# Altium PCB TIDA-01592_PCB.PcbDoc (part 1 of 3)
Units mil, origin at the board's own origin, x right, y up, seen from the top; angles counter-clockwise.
Board outline 2047.24 x 4291.34 mil, 4 copper layers (Top Layer, GND, PWR, Bottom Layer), stack 61.6 mil thick; 218 components, 89 nets, 503 pads, 366 vias.
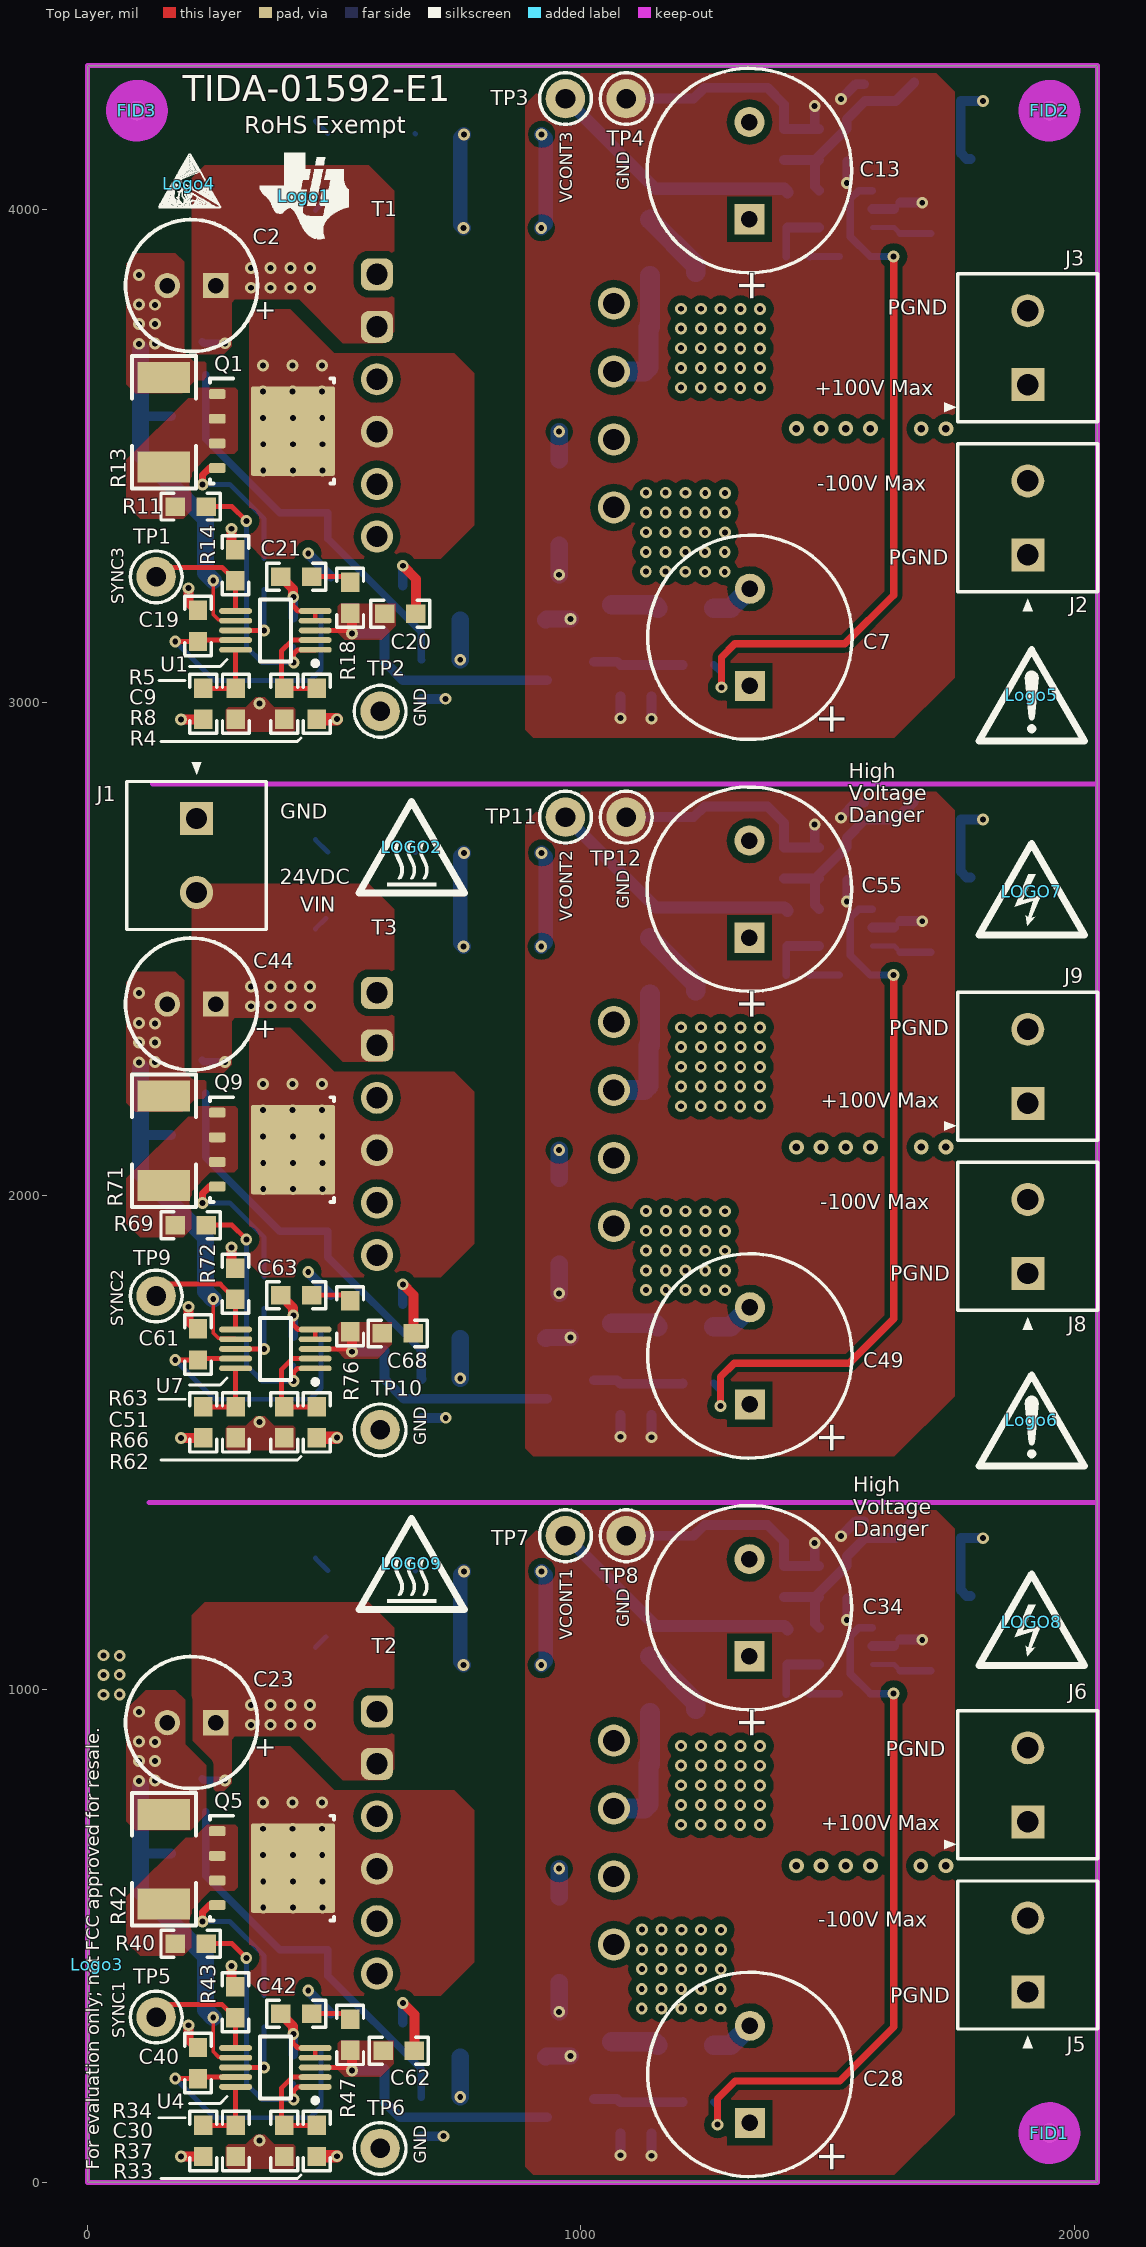
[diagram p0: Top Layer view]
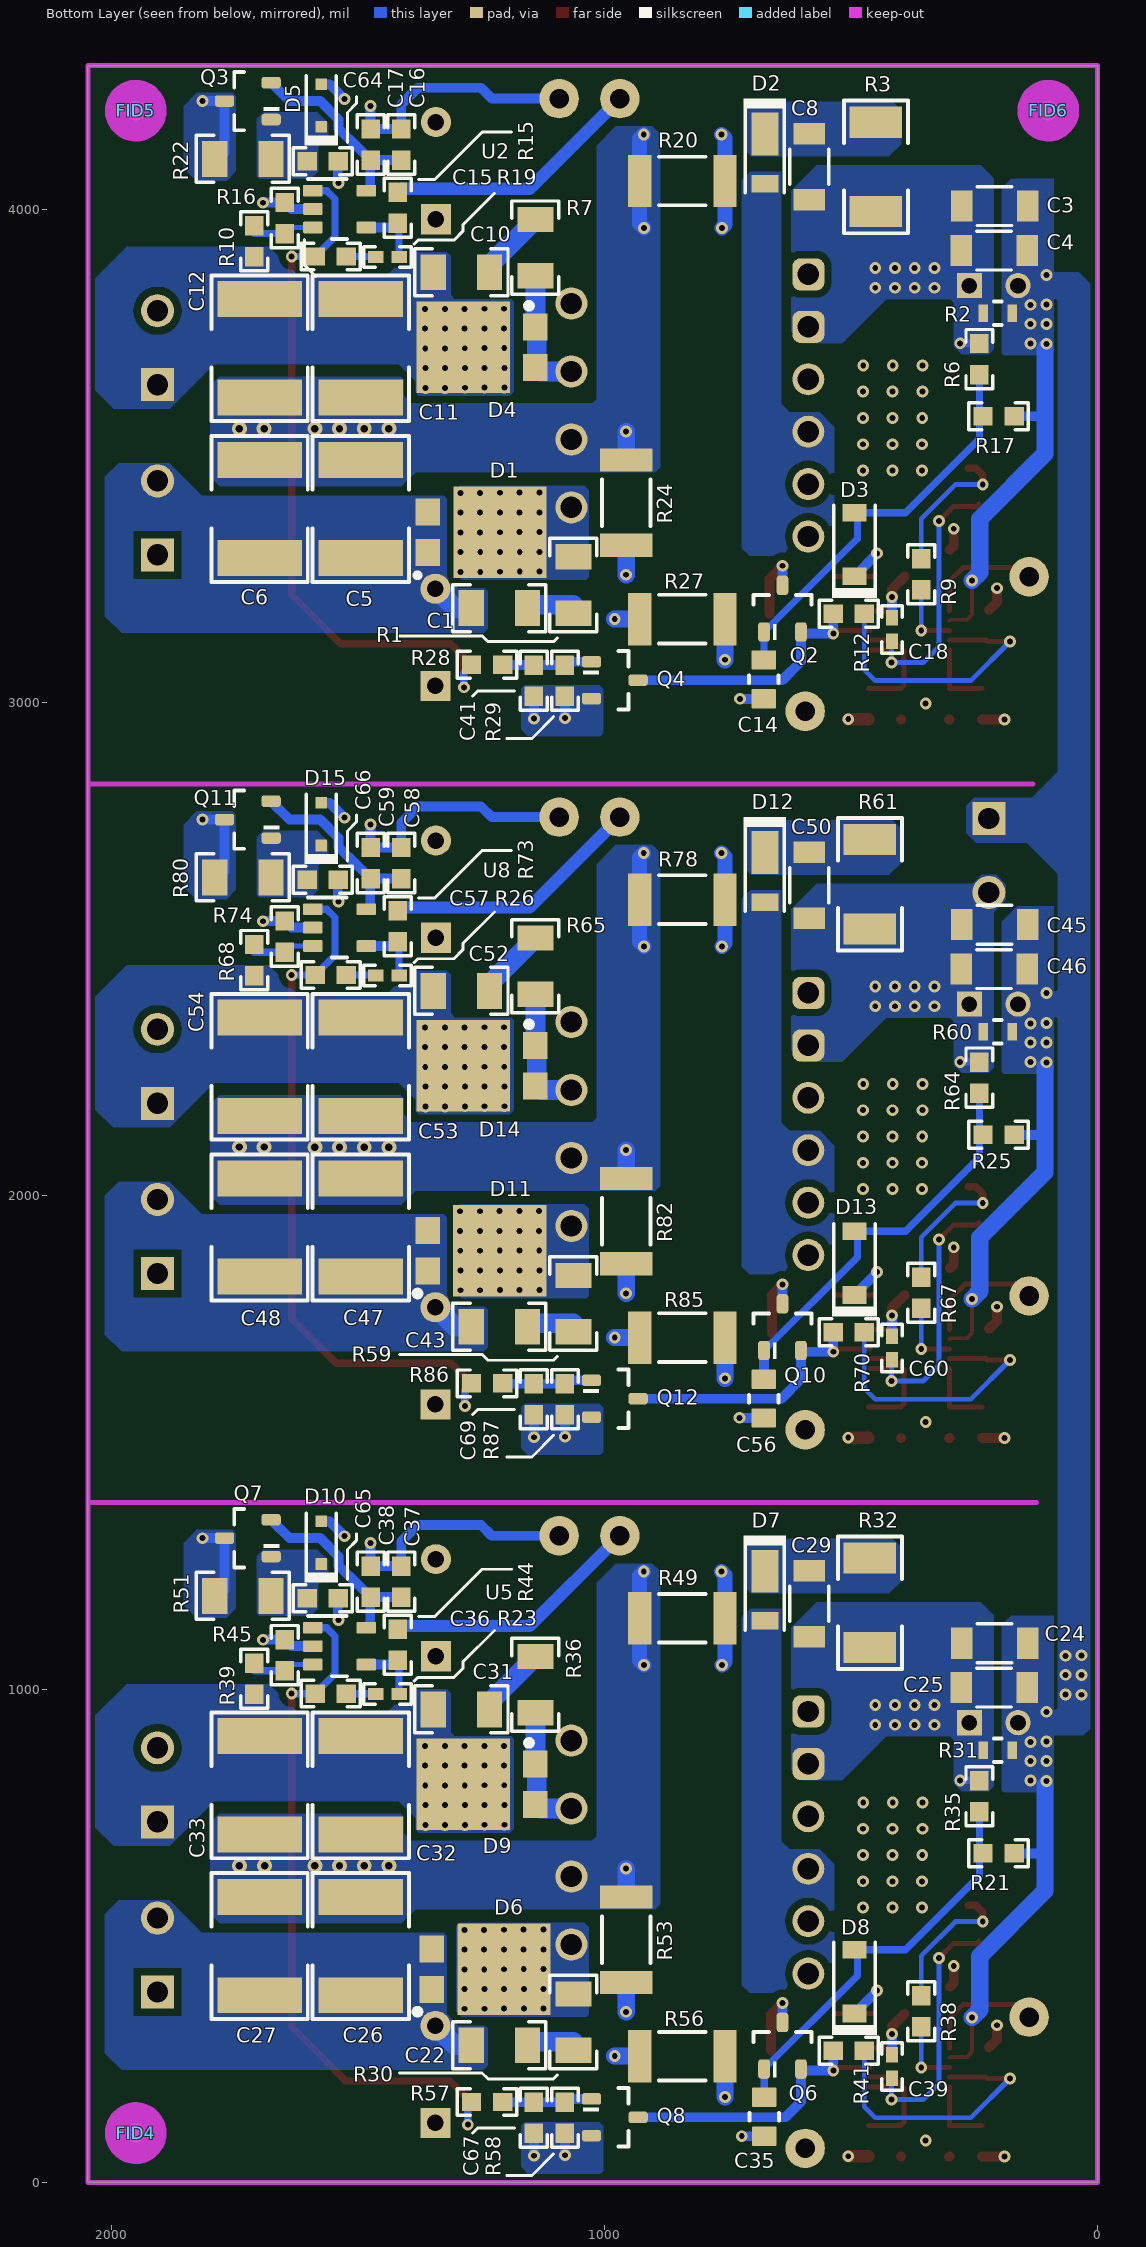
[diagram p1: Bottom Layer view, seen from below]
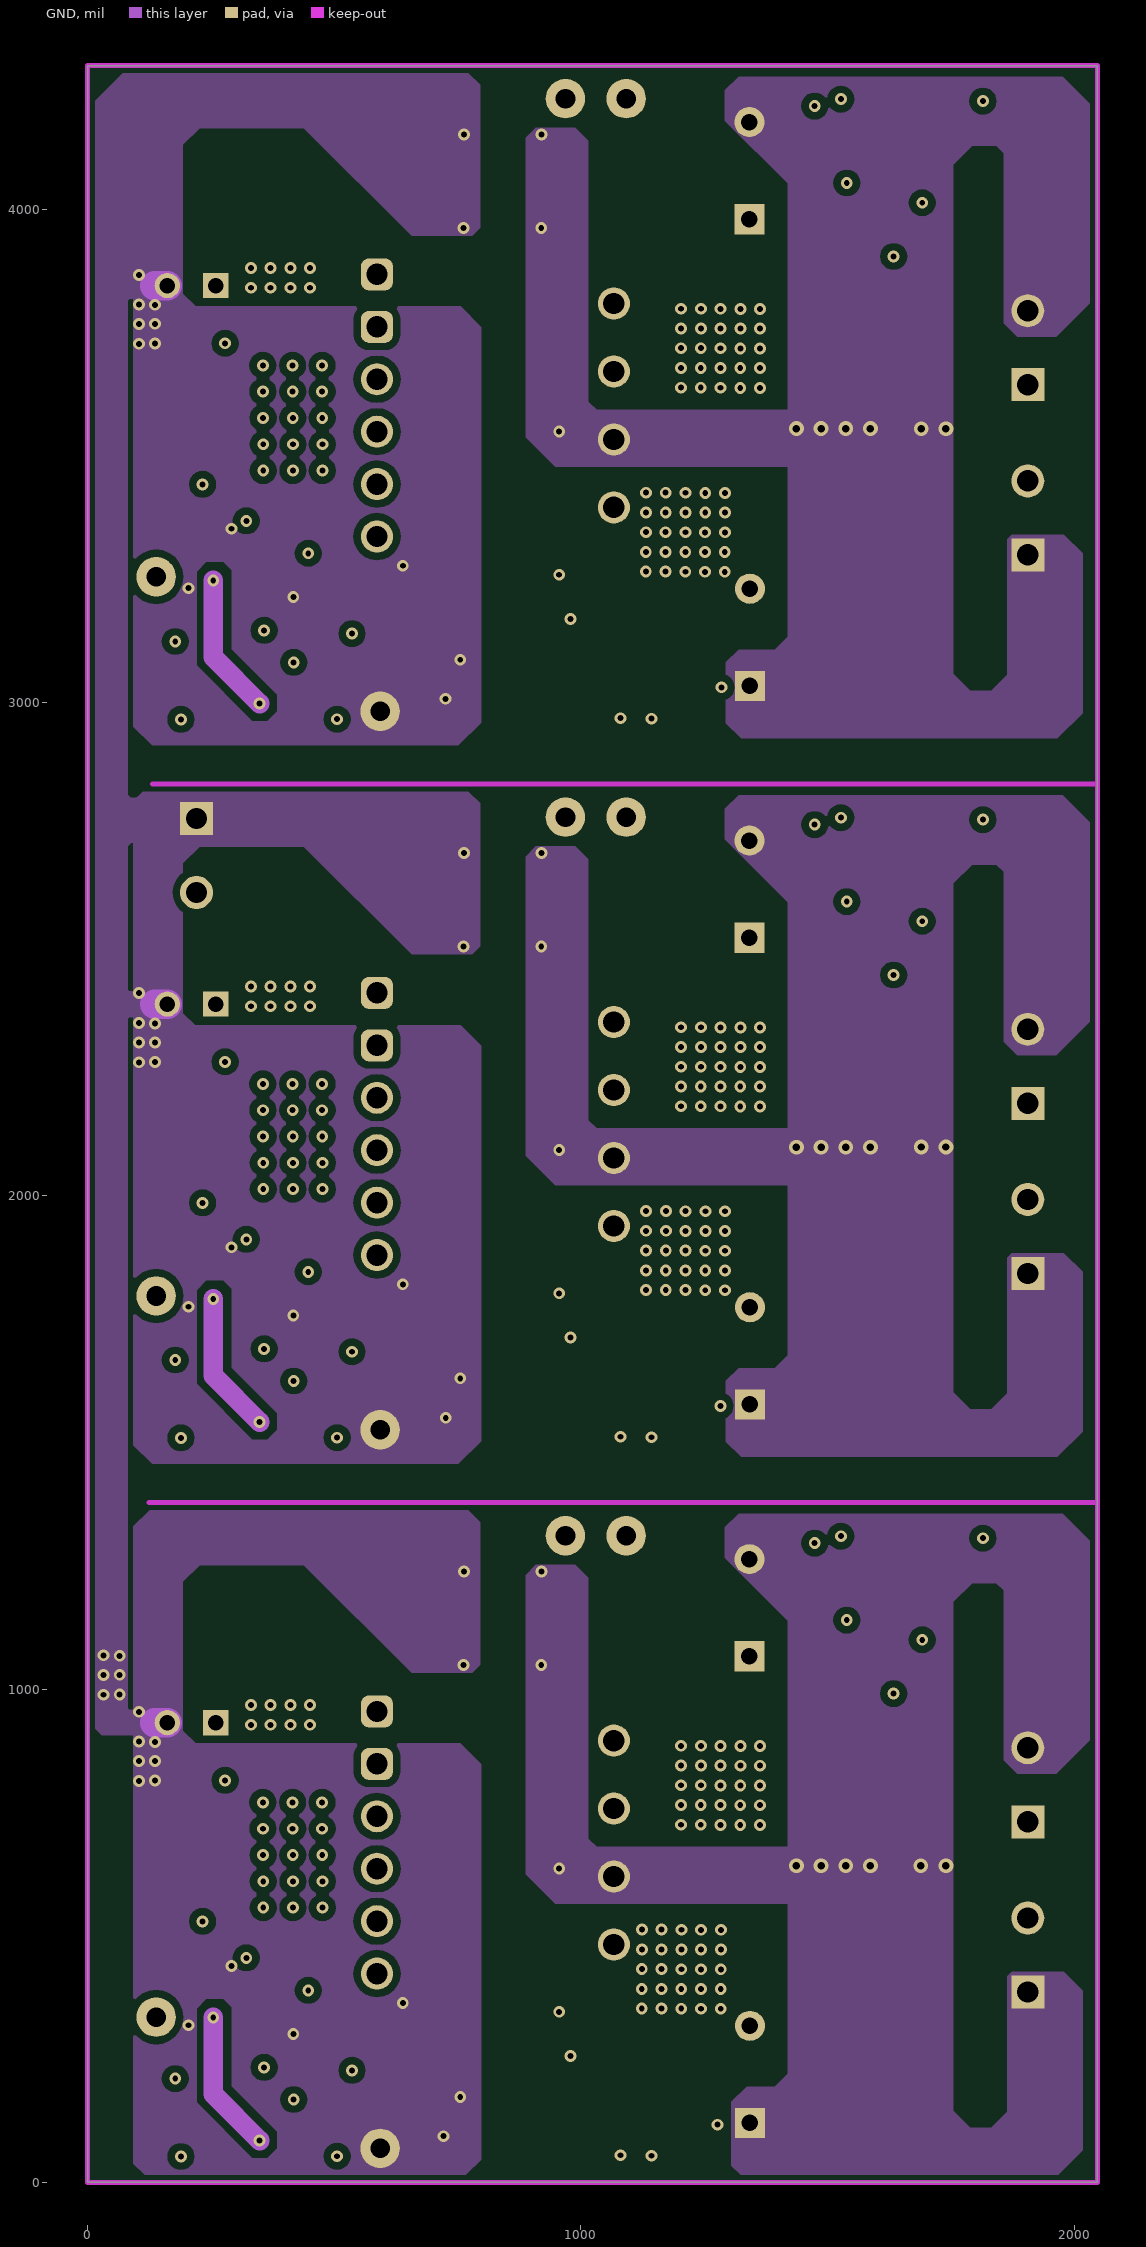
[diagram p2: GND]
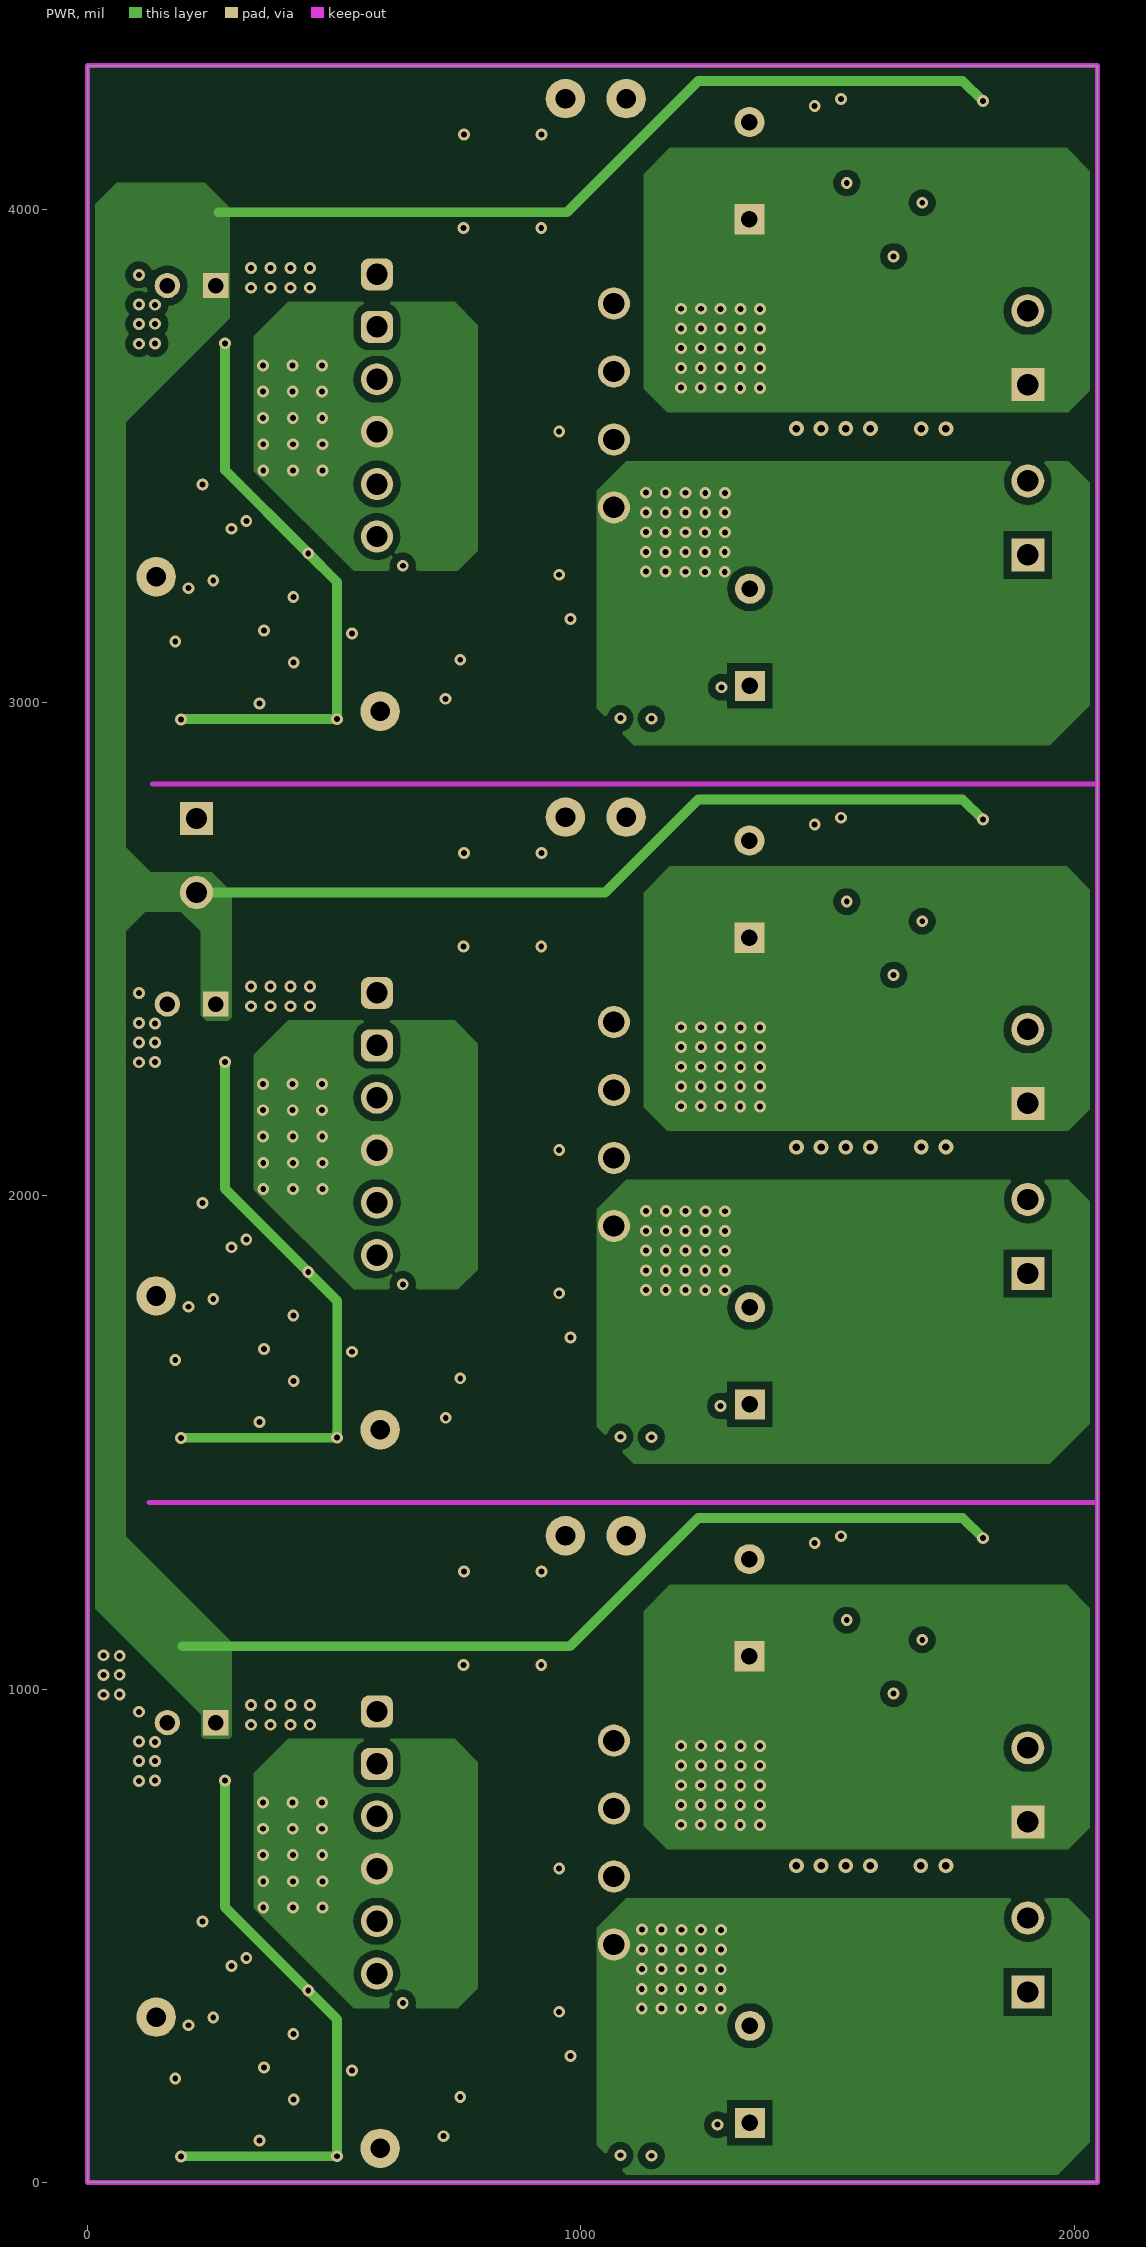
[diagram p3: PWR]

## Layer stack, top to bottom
Top Solder: solder mask 0.4, Solder Resist, Dk 3.5
Top Layer: signal copper 1.4
Dielectric 1: dielectric 10, FR-4 High Tg, Dk 4.2
GND: signal copper 1.4
Dielectric 2: dielectric 36, FR-4 High Tg, Dk 4.2
PWR: signal copper 1.4
Dielectric 3: dielectric 10, FR-4 High Tg, Dk 4.2
Bottom Layer: signal copper 1.4
Bottom Solder: solder mask 0.4, Solder Resist, Dk 3.5

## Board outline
0,0 2047.24,0 2047.24,4291.34 0,4291.34

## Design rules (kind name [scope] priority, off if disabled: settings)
AcuteAngle [All] p1: minimum=4.50000000000000E+0001 checktracksonly=FALSE
AssemblyTestPointUsage [All] p1: valid=2
Clearance Clearance_Keepouts [((IsTrack Or IsArc) And Not InPoly) And IsFree and IsKeepOut vs ((IsTrack Or IsArc) And Not InPoly) And IsFree and IsKeepOut] p1: gap=0 ignorepadtopadclearanceinfootprint=FALSE
Clearance Clearance_Poly [InPolygon] p2: gap=10 ignorepadtopadclearanceinfootprint=FALSE except(0: Arc-Hole Track-Hole SMDPad-Hole THPad-Hole Via-Hole Fill-Hole Poly-Hole Region-Hole Text-Hole; 15: THPad-Poly Via-Poly Poly-Poly)
Clearance [All] p3: gap=7.87 ignorepadtopadclearanceinfootprint=FALSE except(0: Arc-Hole Track-Hole SMDPad-Hole THPad-Hole Via-Hole Fill-Hole Poly-Hole Region-Hole Text-Hole)
ComponentClearance ComponentClearance_MountingHoles_FiducialMarks [InComponentClass('Mounting Holes') vs InComponentClass('FiducialMark')] p1: gap=10 collisioncheckmode=3 verticalgap=10 showdistances=FALSE
ComponentClearance ComponentClearance_Shunt [InComponentClass('Header') vs InComponentClass('Shunt')] p2: gap=0 collisioncheckmode=3 verticalgap=0 showdistances=FALSE
ComponentClearance ComponentClearance_Logo [InComponentClass('Logo')] p3: gap=0 collisioncheckmode=3 verticalgap=0 showdistances=FALSE
ComponentClearance ComponentClearance_ScrewToNut [(HasFootprint('NY PMS 440 0025 PH')) vs (HasFootprint('Keystone_1902C'))] p4: gap=5 collisioncheckmode=3 verticalgap=10 showdistances=FALSE
ComponentClearance ComponentClearance_MountingHoles [InComponentClass('Mounting Holes')] p5: gap=10 collisioncheckmode=3 verticalgap=100000 showdistances=FALSE
ComponentClearance ComponentClearance_SmallPassives [HasFootprint('0201*') or HasFootprint('0402*') or HasFootprint('0508') or HasFootprint('0603*') or HasFootprint('0612') or HasFootprint('0805*') or HasFootprint('0815*') or HasFootprint('0830*') or HasFootprint('1206*') or HasFootprint('1210*') or HasFootprint('1808*') or HasFootprint('1812*') or HasFootprint('1825*') or HasFootprint('2010*') or HasFootprint('2220*') or HasFootprint('2225*') or HasFootprint('2512*') or HasFootprint('2728*') or HasFootprint('3518*') vs HasFootprint('0201*') or HasFootprint('0402*') or HasFootprint('0508') or HasFootprint('0603*') or HasFootprint('0612') or HasFootprint('0805*') or HasFootprint('0815*') or HasFootprint('0830*') or HasFootprint('1206*') or HasFootprint('1210*') or HasFootprint('1808*') or HasFootprint('1812*') or HasFootprint('1825*') or HasFootprint('2010*') or HasFootprint('2220*') or HasFootprint('2225*') or HasFootprint('2512*') or HasFootprint('2728*') or HasFootprint('3518*')] p6: gap=10 collisioncheckmode=3 verticalgap=10 showdistances=FALSE
ComponentClearance ComponentClearance_THtoSMT [IsThruComponent vs IsSMTComponent] p7: gap=10 collisioncheckmode=3 verticalgap=10 showdistances=FALSE
ComponentClearance ComponentClearance_THtoTH [IsThruComponent vs IsThruComponent] p8: gap=10 collisioncheckmode=3 verticalgap=10 showdistances=FALSE
ComponentClearance [All] p9: gap=10 collisioncheckmode=3 verticalgap=10 showdistances=FALSE
DiffPairsRouting [All] p1: maxlimit=100 minlimit=10 mostfreqgap=10 toplayer_minwidth=15 toplayer_maxwidth=15 toplayer_prefwidth=15 midlayer1_minwidth=15 midlayer1_maxwidth=15 midlayer1_prefwidth=15 midlayer2_minwidth=15 midlayer2_maxwidth=15 midlayer2_prefwidth=15 bottomlayer_minwidth=15 bottomlayer_maxwidth=15 bottomlayer_prefwidth=15 maxuncoupledlength=1000
FabricationTestPointUsage TestPointUsage [All] p1: valid=2 allowmultiple=FALSE
FabricationTestpoint Testpoint [All] p1: side=3 testpointundercomponent=TRUE minsize=40 maxsize=100 preferedsize=60 minholesize=0 maxholesize=40 preferedholesize=32 testpointgrid=1 allowsidetop=TRUE allowsidebottom=TRUE usegrid=TRUE gridtolerance=0.01
FanoutControl Fanout_LCC [IsLCC] p1: bgadir=Out bgaviamode=Centered fanoutstyle=Auto fanoutdirection=Alternating viagrid=1 // Fanout_LCC (Default Rule)
FanoutControl Fanout_BGA [IsBGA] p2: bgadir=Out bgaviamode=Centered fanoutstyle=Auto fanoutdirection=Alternating viagrid=1 // Fanout_BGA (Default Rule)
FanoutControl Fanout_Default [All] p4: bgadir=Out bgaviamode=Centered fanoutstyle=Auto fanoutdirection=Alternating viagrid=1 // Fanout_Default (Default Rule)
FanoutControl Fanout_Small [(CompPinCount < 5)] p5: bgadir=Out bgaviamode=Centered fanoutstyle=Auto fanoutdirection=OutThenIn viagrid=1 // Fanout_Small (Default Rule)
HoleSize [All] p1: absolutevalues=TRUE maxlimit=251 minlimit=7.87 maxpercent=80.000 minpercent=20.000
MinimumAnnularRing MinimumAnnularRing_ThermalPadVias [IsVia and InAnyComponent] p1: minimumring=5.91
MinimumAnnularRing [All] p2: minimumring=6
MinimumSolderMaskSliver MinimumSolderMaskSliver_Logo [InComponentClass('Logo') vs InComponentClass('Logo')] p1: minsoldermaskwidth=0.7
MinimumSolderMaskSliver [All] p2: minsoldermaskwidth=3.94
PlaneConnect [All] p1: planeconnectstyle=Relief reliefexpansion=10 reliefentries=4 reliefconductorwidth=10 reliefairgap=10
PolygonConnect [All] p1: connectstyle=Direct reliefconductorwidth=10 reliefentries=4 polygonreliefangle="90 Angle" airgapwidth=10
RoutingVias ThermalPadVias [IsVia and InAnyComponent] p1: holewidth=7.87 width=19.68 viastyle="Through Hole" minholewidth=7.87 minwidth=19.68 maxholewidth=12.99 maxwidth=23.62
RoutingVias [All] p2: holewidth=12 width=24 viastyle="Through Hole" minholewidth=10 minwidth=20 maxholewidth=40 maxwidth=65
SilkToBoardRegionClearance [Not ((IsComment or IsDesignator) And (Hide <> 'False')) and not InRegion(1000,500,4000,800)] p1:
SilkToSilkClearance SilkToSilkClearance_Pb-FreeLogo [(HasFootprint('Pb-Free_Overlay_Medium') OR HasFootprint('Pb-Free_Overlay_Small')) vs (HasFootprint('Pb-Free_Overlay_Medium') OR HasFootprint('Pb-Free_Overlay_Small'))] p1: silktosilkclearance=0
SilkToSilkClearance [All] p2: silktosilkclearance=4
SilkToSolderMaskClearance SilkToComponentPadClearance [(IsPad or IsFill or IsRegion) and InAnycomponent] p1: minsilkscreentomaskgap=5 clearancetoexposedcopper=TRUE
SilkToSolderMaskClearance "Silk to Solder Mask Opening" [All] p2: minsilkscreentomaskgap=4 clearancetoexposedcopper=FALSE
SolderMaskExpansion [All] p1: expansion=1.97
Width [All] p1: maxlimit=100 minlimit=6 preferedwidth=10 checkconnectedcopper=TRUE
15 further rules are at their usual default settings.

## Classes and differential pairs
component class "TIDA-01592_Power Supply2": C43 C44 C45 C46 C47 C48 C49 C50 C51 C52 C53 C54 C55 C56 C57 C58 C59 C60 C61 C63 C66 C68 C69 D11 D12 D13 D14 D15 J8 J9 Q9 Q10 Q11 Q12 R25 R26 R59 R60 R61 R62 R63 R64 R65 R66 R67 R68 R69 R70 R71 R72 R73 R74 R76 R78 R80 R82 R85 R86 R87 T3 TP9 TP10 TP11 TP12 U7 U8
component class "TIDA-01592_Power Supply3": C1 C2 C3 C4 C5 C6 C7 C8 C9 C10 C11 C12 C13 C14 C15 C16 C17 C18 C19 C20 C21 C41 C64 D1 D2 D3 D4 D5 J2 J3 Q1 Q2 Q3 Q4 R1 R2 R3 R4 R5 R6 R7 R8 R9 R10 R11 R12 R13 R14 R15 R16 R17 R18 R19 R20 R22 R24 R27 R28 R29 T1 TP1 TP2 TP3 TP4 U1 U2
component class "TIDA-01592_Power Supply1": C22 C23 C24 C25 C26 C27 C28 C29 C30 C31 C32 C33 C34 C35 C36 C37 C38 C39 C40 C42 C62 C65 C67 D6 D7 D8 D9 D10 J1 J5 J6 Q5 Q6 Q7 Q8 R21 R23 R30 R31 R32 R33 R34 R35 R36 R37 R38 R39 R40 R41 R42 R43 R44 R45 R46 R47 R49 R51 R53 R56 R57 R58 T2 TP5 TP6 TP7 TP8 U4 U5
component class AssemblyNote: ZZ1 ZZ2 ZZ3 ZZ4
component class TIDA-01592_Hardware: FID1 FID2 FID3 FID4 FID5 FID6 Logo1 LOGO2 Logo3 Logo4 Logo5 Logo6 LOGO7 LOGO8 LOGO9 ZZ1 ZZ2 ZZ3 ZZ4
component class Logo: Logo1
component class FiducialMark: FID1 FID2 FID3 FID4 FID5 FID6

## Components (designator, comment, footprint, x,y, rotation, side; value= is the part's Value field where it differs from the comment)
C1 "12067A330JAT2A" 1206 1213,3191.39 r180 bottom value=33pF
C2 "35TXW180MEFC6.3X25" FC_630x1120 210.74,3845.39 r180 top value=180uF
C3 "GRM31CR61H106KA12L" 1206_180 209,4006.39 r180 bottom value=10uF
C4 "GRM31CR61H106KA12L" 1206_180 210,3916.39 r180 bottom value=10uF
C5 "C4532X7T2E105M250KE" 1812_180 1494,3392.39 r90 bottom value=1uF
C6 "C4532X7T2E105M250KE" 1812_180 1699,3392.39 r90 bottom value=1uF
C7 "UCY2C820MPD9" NHG_1000x2000 1342.74,3132.39 r90 top value=82uF
C8 "GRM31CR72A105KA01L" 1206_180 584.74,4086.39 r90 bottom value=1uF
C9 "GRM188R71H104KA93D" 0603 300.74,2997.39 r90 top value=0.1uF
C10 "12067A330JAT2A" 1206 1290,3872.39 r180 bottom value=33pF
C11 "C4532X7T2E105M250KE" 1812_180 1494,3718.39 r90 bottom value=1uF
C12 "C4532X7T2E105M250KE" 1812_180 1699,3718.39 r90 bottom value=1uF
C13 "UCY2C820MPD9" NHG_1000x2000 1341.74,4078.39 r90 top value=82uF
C14 "C2012X5R1V226M125AC" 0805_HV1 677,3047 r270 bottom value=22uF
C15 "GRM188R71H104KA93D" 0603 1555,3904.39 r180 bottom value=0.1uF
C16 "UMK107AB7105KA-T" 0603 1412,4131.39 r90 bottom value=1uF
C17 "GRM188R71H104KA93D" 0603 1474,4131.39 r90 bottom value=0.1uF
C18 "GRM155R61H222KA01D" 0402 417,3148.39 r90 bottom value=2200pF
C19 "0603ZD475KAT2A" 0603 223.74,3155.39 r90 top value=4.7uF
C20 "GRM188R71H104KA93D" 0603 634,3180 r180 top value=0.1uF
C21 "C0603C105K3RACTU" 0603 422.74,3255.39 r180 top value=1uF
C22 "12067A330JAT2A" 1206 1213,278 r180 bottom value=33pF
C23 "35TXW180MEFC6.3X25" FC_630x1120 210.74,932 r180 top value=180uF
C24 "GRM31CR61H106KA12L" 1206_180 209,1093 r180 bottom value=10uF
C25 "GRM31CR61H106KA12L" 1206_180 210,1003 r180 bottom value=10uF
C26 "C4532X7T2E105M250KE" 1812_180 1494,479 r90 bottom value=1uF
C27 "C4532X7T2E105M250KE" 1812_180 1699,479 r90 bottom value=1uF
C28 "UCY2C820MPD9" NHG_1000x2000 1342.74,219 r90 top value=82uF
C29 "GRM31CR72A105KA01L" 1206_180 584.74,1173 r90 bottom value=1uF
C30 "GRM188R71H104KA93D" 0603 300.74,84 r90 top value=0.1uF
C31 "12067A330JAT2A" 1206 1290,959 r180 bottom value=33pF
C32 "C4532X7T2E105M250KE" 1812_180 1494,805 r90 bottom value=1uF
C33 "C4532X7T2E105M250KE" 1812_180 1699,805 r90 bottom value=1uF
C34 "UCY2C820MPD9" NHG_1000x2000 1341.74,1165 r90 top value=82uF
C35 "C2012X5R1V226M125AC" 0805_HV1 676,133 r270 bottom value=22uF
C36 "GRM188R71H104KA93D" 0603 1555,991 r180 bottom value=0.1uF
C37 "UMK107AB7105KA-T" 0603 1412,1218 r90 bottom value=1uF
C38 "GRM188R71H104KA93D" 0603 1474,1218 r90 bottom value=0.1uF
C39 "GRM155R61H222KA01D" 0402 417,235 r90 bottom value=2200pF
C40 "0603ZD475KAT2A" 0603 223.74,242 r90 top value=4.7uF
C41 "GRM188R71H104KA93D" 0603 1143,3044.39 r90 bottom value=0.1uF
C42 "C0603C105K3RACTU" 0603 422.74,342 r180 top value=1uF
C43 "12067A330JAT2A" 1206 1213,1734.69 r180 bottom value=33pF
C44 "35TXW180MEFC6.3X25" FC_630x1120 210.74,2388.69 r180 top value=180uF
C45 "GRM31CR61H106KA12L" 1206_180 209,2549.69 r180 bottom value=10uF
C46 "GRM31CR61H106KA12L" 1206_180 210,2459.69 r180 bottom value=10uF
C47 "C4532X7T2E105M250KE" 1812_180 1494,1935.69 r90 bottom value=1uF
C48 "C4532X7T2E105M250KE" 1812_180 1699,1935.69 r90 bottom value=1uF
C49 "UCY2C820MPD9" NHG_1000x2000 1342.74,1675.69 r90 top value=82uF
C50 "GRM31CR72A105KA01L" 1206_180 584.74,2629.69 r90 bottom value=1uF
C51 "GRM188R71H104KA93D" 0603 300.74,1540.69 r90 top value=0.1uF
C52 "12067A330JAT2A" 1206 1290,2415.69 r180 bottom value=33pF
C53 "C4532X7T2E105M250KE" 1812_180 1494,2261.69 r90 bottom value=1uF
C54 "C4532X7T2E105M250KE" 1812_180 1699,2261.69 r90 bottom value=1uF
C55 "UCY2C820MPD9" NHG_1000x2000 1341.74,2621.69 r90 top value=82uF
C56 "C2012X5R1V226M125AC" 0805_HV1 677,1589 r270 bottom value=22uF
C57 "GRM188R71H104KA93D" 0603 1555,2447.69 r180 bottom value=0.1uF
C58 "UMK107AB7105KA-T" 0603 1412,2674.69 r90 bottom value=1uF
C59 "GRM188R71H104KA93D" 0603 1474,2674.69 r90 bottom value=0.1uF
C60 "GRM155R61H222KA01D" 0402 417,1691.69 r90 bottom value=2200pF
C61 "0603ZD475KAT2A" 0603 223.74,1698.69 r90 top value=4.7uF
C62 "GRM188R71H104KA93D" 0603 631,267 r180 top value=0.1uF
C63 "C0603C105K3RACTU" 0603 422.74,1798.69 r180 top value=1uF
C64 "C0603C105K3RACTU" 0603 1571,4097.39 r180 bottom value=1uF
C65 "C0603C105K3RACTU" 0603 1571,1184 r180 bottom value=1uF
C66 "C0603C105K3RACTU" 0603 1571,2640.69 r180 bottom value=1uF
C67 "GRM188R71H104KA93D" 0603 1143,131 r90 bottom value=0.1uF
C68 "GRM188R71H104KA93D" 0603 629,1721 r180 top value=0.1uF
C69 "GRM188R71H104KA93D" 0603 1143,1587.69 r90 bottom value=0.1uF
D1 "VS-6ESH06HM3/86A" TO-277A 1285.95,3345.33 r90 bottom value=600V
D2 "DFLS1100-7" PowerDI123 674.74,4102.39 r270 bottom value=100V
D3 "BAT42W-7-F" SOD-123 493,3320.39 r90 bottom value=30V
D4 "VS-6ESH06HM3/86A" TO-277A 1212,3720.39 r270 bottom value=600V
D5 "MMSZ5242BS-7-F" SOD-323 1574,4210.39 r90 bottom value=12V
D6 "VS-6ESH06HM3/86A" TO-277A 1277.71,432.15 r90 bottom value=600V
D7 "DFLS1100-7" PowerDI123 674.74,1189 r270 bottom value=100V
D8 "BAT42W-7-F" SOD-123 493,407 r90 bottom value=30V
D9 "VS-6ESH06HM3/86A" TO-277A 1212,807 r270 bottom value=600V
D10 "MMSZ5242BS-7-F" SOD-323 1574,1297 r90 bottom value=12V
D11 "VS-6ESH06HM3/86A" TO-277A 1286.33,1888.89 r90 bottom value=600V
D12 "DFLS1100-7" PowerDI123 674.74,2645.69 r270 bottom value=100V
D13 "BAT42W-7-F" SOD-123 493,1863.69 r90 bottom value=30V
D14 "VS-6ESH06HM3/86A" TO-277A 1212,2263.69 r270 bottom value=600V
D15 "MMSZ5242BS-7-F" SOD-323 1574,2753.69 r90 bottom value=12V
FID1 "Fiducial" Fiducial10-30 1950,100 r0 top
FID2 "Fiducial" Fiducial10-30 1950,4200 r90 top
FID3 "Fiducial" Fiducial10-30 100,4200 r90 top
FID4 "Fiducial" Fiducial10-30 1950,100 r90 bottom
FID5 "Fiducial" Fiducial10-30 1950,4200 r90 bottom
FID6 "Fiducial" Fiducial10-30 100,4200 r90 bottom
J1 "1727010" PhoenixConact_1727010 220.74,2690 r270 top
J2 "1727010" PhoenixConact_1727010 1906,3374.39 r90 top
J3 "1727010" PhoenixConact_1727010 1906,3719.39 r90 top
J5 "1727010" PhoenixConact_1727010 1906,461 r90 top
J6 "1727010" PhoenixConact_1727010 1906,806 r90 top
J8 "1727010" PhoenixConact_1727010 1906,1917.69 r90 top
J9 "1727010" PhoenixConact_1727010 1906,2262.69 r90 top
Logo1 "Texas Instruments" TI_Symbol_Overlay_Small 439,4027 r0 top
LOGO2 "CAUTION HOT SURFACE" IEC_HotSurface_Small 657,2707 r0 top
Logo3 "FCC disclaimer" FCC_disclaimer 20,441 r270 top
Logo4 "ESD Susceptible" ESD_Overlay_Small 206,4052 r0 top
Logo5 "CAUTION.  READ USER GUIDE BEFORE USE" IEC_Caution_Small 1914,3015 r0 top
Logo6 "CAUTION.  READ USER GUIDE BEFORE USE" IEC_Caution_Small 1914,1545 r0 top
LOGO7 "DANGER HIGH VOLTAGE" IEC_HighVoltage_Small 1914,2617 r0 top
LOGO8 "DANGER HIGH VOLTAGE" IEC_HighVoltage_Small 1914,1136 r0 top
LOGO9 "CAUTION HOT SURFACE" IEC_HotSurface_Small 657,1254 r0 top
Q1 "CSD19532Q5B" DNK0008A 373.74,3550.39 r0 top value=100V
Q2 "MMBT2907ALT1G" SOT-23 639,3190.39 r90 bottom value="60 V"
Q3 "DNBT8105-7" SOT-23 1723,4219.39 r0 bottom value="60 V"
Q4 "DNBT8105-7" SOT-23 979,3045.39 r180 bottom value="60 V"
Q5 "CSD19532Q5B" DNK0008A 373.74,637 r0 top value=100V
Q6 "MMBT2907ALT1G" SOT-23 639,277 r90 bottom value="60 V"
Q7 "DNBT8105-7" SOT-23 1723,1306 r0 bottom value="60 V"
Q8 "DNBT8105-7" SOT-23 979,132 r180 bottom value="60 V"
Q9 "CSD19532Q5B" DNK0008A 373.74,2093.69 r0 top value=100V
Q10 "MMBT2907ALT1G" SOT-23 639,1733.69 r90 bottom value="60 V"
Q11 "DNBT8105-7" SOT-23 1723,2762.69 r0 bottom value="60 V"
Q12 "DNBT8105-7" SOT-23 979,1588.69 r180 bottom value="60 V"
R1 "CRCW1206470RJNEA" 1206 1063,3238.39 r270 bottom value=470
R2 "TNPW06035K11BEEA" TNPW0603 202.74,3789.39 r0 bottom value=5.11k
R3 "CRCW20102K61FKEF" 2010 449.58,4086.01 r270 bottom value=2.61k
R4 "CRCW0603402KFKEA" 0603 464.74,2997.39 r270 top value=402k
R5 "CRCW060310R0FKEAHP" 0603 234.74,2997.39 r90 top value=10.0
R6 "CRCW06031M00JNEA" 0603 239.71,3696.42 r90 bottom value=1.0Meg
R7 "CRCW1206470RJNEA" 1206 1140,3922.39 r90 bottom value=470
R8 "CRCW060366K5FKEA" 0603 398.74,2997.39 r90 top value=66.5k
R9 "CRCW06034R70JNEA" 0603 357.74,3260.39 r90 bottom value=4.7
R10 "CRCW0603191KFKEA" 0603 1710,3935 r270 bottom value=191k
R11 "CRCW0603300RJNEA" 0603 208.74,3397.39 r180 top value=300
R12 "ERJ-3GEYJ222V" 0603 504.74,3180.39 r180 bottom value=2.2k
R13 "WSL2010R0150FEA18" 2010 154.74,3568.39 r270 top value=0.015
R14 "RT0603DRE07172KL" 0603 299.74,3278.39 r270 top value=172k
R15 "CRCW060322K0JNEA" 0603 1419,4003.39 r90 bottom value=22k
R16 "CRCW060310K0FKEA" 0603 1647.74,3982.39 r90 bottom value=10.0k
R17 "CRCW0603390KJNEA" 0603 201,3580.39 r0 bottom value=390k
R18 "CRCW06031K00JNEA" 0603 532,3212.39 r270 top value=1.0k
R19 "CRCW04020000Z0ED" 0402 1440,3903.39 r180 bottom value=0
R20 "CRCW20100000Z0EF" 2010L 842,4057.39 r0 bottom value=0
R21 "CRCW0603390KJNEA" 0603 201,667 r0 bottom value=390k
R22 "CRCW120647K0JNEA" 1206 1733,4102.39 r0 bottom value=47k
R23 "CRCW04020000Z0ED" 0402 1440,990 r180 bottom value=0
R24 "CRCW20100000Z0EF" 2010L 956,3405.39 r90 bottom value=0
R25 "CRCW0603390KJNEA" 0603 201,2123.69 r0 bottom value=390k
R26 "CRCW04020000Z0ED" 0402 1440,2446.69 r180 bottom value=0
R27 "CRCW20100000Z0EF" 2010L 842,3169.39 r0 bottom value=0
R28 "RC0603JR-0747KL" 0603 1238,3076.39 r180 bottom value=47k
R29 "RC0603JR-0747KL" 0603 1080,3044.39 r270 bottom value=47k
R30 "CRCW1206470RJNEA" 1206 1063,325 r270 bottom value=470
R31 "TNPW06035K11BEEA" TNPW0603 202.74,876 r0 bottom value=5.11k
R32 "CRCW20102K61FKEF" 2010 461.74,1175 r270 bottom value=2.61k
R33 "CRCW0603402KFKEA" 0603 464.74,84 r270 top value=402k
R34 "CRCW060310R0FKEAHP" 0603 234.74,84 r90 top value=10.0
R35 "CRCW06031M00JNEA" 0603 239.71,783.03 r90 bottom value=1.0Meg
R36 "CRCW1206470RJNEA" 1206 1140,1009 r90 bottom value=470
R37 "CRCW060366K5FKEA" 0603 398.74,84 r90 top value=66.5k
R38 "CRCW06034R70JNEA" 0603 357.74,347 r90 bottom value=4.7
R39 "CRCW0603191KFKEA" 0603 1710,1021 r270 bottom value=191k
R40 "CRCW0603300RJNEA" 0603 208.74,484 r180 top value=300
R41 "ERJ-3GEYJ222V" 0603 504.74,267 r180 bottom value=2.2k
R42 "WSL2010R0150FEA18" 2010 154.74,655 r270 top value=0.015
R43 "RT0603DRE07172KL" 0603 299.74,365 r270 top value=172k
R44 "CRCW060322K0JNEA" 0603 1419,1090 r90 bottom value=22k
R45 "CRCW060310K0FKEA" 0603 1647.74,1069 r90 bottom value=10.0k
R47 "CRCW06031K00JNEA" 0603 532,299 r270 top value=1.0k
R49 "CRCW20100000Z0EF" 2010L 842,1144 r0 bottom value=0
R51 "CRCW120647K0JNEA" 1206 1733,1189 r0 bottom value=47k
R53 "CRCW20100000Z0EF" 2010L 956,492 r90 bottom value=0
R56 "CRCW20100000Z0EF" 2010L 842,256 r0 bottom value=0
R57 "RC0603JR-0747KL" 0603 1238,163 r180 bottom value=47k
R58 "RC0603JR-0747KL" 0603 1080,131 r270 bottom value=47k
R59 "CRCW1206470RJNEA" 1206 1063,1781.69 r270 bottom value=470
R60 "TNPW06035K11BEEA" TNPW0603 202.74,2332.69 r0 bottom value=5.11k
R61 "CRCW20102K61FKEF" 2010 461.74,2631.69 r270 bottom value=2.61k
R62 "CRCW0603402KFKEA" 0603 464.74,1540.69 r270 top value=402k
R63 "CRCW060310R0FKEAHP" 0603 234.74,1540.69 r90 top value=10.0
R64 "CRCW06031M00JNEA" 0603 239.71,2239.72 r90 bottom value=1.0Meg
R65 "CRCW1206470RJNEA" 1206 1140,2465.69 r90 bottom value=470
R66 "CRCW060366K5FKEA" 0603 398.74,1540.69 r90 top value=66.5k
R67 "CRCW06034R70JNEA" 0603 357.74,1803.69 r90 bottom value=4.7
R68 "CRCW0603191KFKEA" 0603 1710,2478 r270 bottom value=191k
R69 "CRCW0603300RJNEA" 0603 208.74,1940.69 r180 top value=300
R70 "ERJ-3GEYJ222V" 0603 504.74,1723.69 r180 bottom value=2.2k
R71 "WSL2010R0150FEA18" 2010 154.74,2111.69 r270 top value=0.015
R72 "RT0603DRE07172KL" 0603 299.74,1821.69 r270 top value=172k
R73 "CRCW060322K0JNEA" 0603 1419,2546.69 r90 bottom value=22k
R74 "CRCW060310K0FKEA" 0603 1647.74,2525.69 r90 bottom value=10.0k
R76 "CRCW06031K00JNEA" 0603 532,1755.69 r270 top value=1.0k
R78 "CRCW20100000Z0EF" 2010L 842,2600.69 r0 bottom value=0
R80 "CRCW120647K0JNEA" 1206 1733,2645.69 r0 bottom value=47k
R82 "CRCW20100000Z0EF" 2010L 956,1948.69 r90 bottom value=0
R85 "CRCW20100000Z0EF" 2010L 842,1712.69 r0 bottom value=0
R86 "RC0603JR-0747KL" 0603 1238,1619.69 r180 bottom value=47k
R87 "RC0603JR-0747KL" 0603 1080,1587.69 r270 bottom value=47k
T1 "750343772" Wurth_EE16_7_5_5278 826.77,3602.36 r0 top value=13uH
T2 "750343772" Wurth_EE16_7_5_5278 826.77,688.98 r0 top value=13uH
T3 "750343772" Wurth_EE16_7_5_5278 826.77,2145.67 r0 top value=13uH
TP1 "5002" Keystone5002 139,3255 r90 top
TP2 "5002" Keystone5002 593,2982.39 r90 top
TP3 "5002" Keystone5002 968.74,4224.39 r90 top
TP4 "5002" Keystone5002 1091.74,4224.39 r90 top
TP5 "5002" Keystone5002 139,335 r90 top
TP6 "5002" Keystone5002 593,69 r90 top
TP7 "5002" Keystone5002 968.74,1311 r90 top
TP8 "5002" Keystone5002 1091.74,1311 r90 top
TP9 "5002" Keystone5002 139,1797 r90 top
TP10 "5002" Keystone5002 593,1525.69 r90 top
TP11 "5002" Keystone5002 968.74,2767.69 r90 top
TP12 "5002" Keystone5002 1091.74,2767.69 r90 top
U1 "LM3481MMX/NOPB" MUB10A_N 380.74,3146.39 r180 top
U2 "TLV171IDBVR" DBV0005A_N 1536.92,4000.58 r180 bottom
U4 "LM3481MMX/NOPB" MUB10A_N 380.74,233 r180 top
U5 "TLV171IDBVR" DBV0005A_N 1536.92,1087.2 r180 bottom
U7 "LM3481MMX/NOPB" MUB10A_N 380.74,1689.69 r180 top
U8 "TLV171IDBVR" DBV0005A_N 1536.92,2543.89 r180 bottom
ZZ1 "This Assembly Note is for PCB labels only" AssemblyNoteLabel 228.74,7027 r0 top
ZZ2 "These assemblies are ESD sensitive, ESD precautions shall be observed." AssemblyNote 228.74,6862 r0 top
ZZ3 "These assemblies must be clean and free from flux and all contaminants. Use of no clean flux is not acceptable." AssemblyNote 239.74,6707 r0 top
ZZ4 "These assemblies must comply with workmanship standards IPC-A-610 Class 2, unless otherwise specified." AssemblyNote 239.74,6542 r0 top

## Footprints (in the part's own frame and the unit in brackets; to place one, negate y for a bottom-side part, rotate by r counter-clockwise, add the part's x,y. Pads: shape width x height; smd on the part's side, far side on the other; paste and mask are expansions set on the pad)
0402 [mm] "0402 from SM-752 data"
  rect 0.8x0.6 smd: 1(-0.6,0) 2(0.6,0)
  silkscreen extent -1.22,-0.52 1.22,0.52, body extent -0.55,-0.3 0.55,0.3, height 0.6
0603 [mm] "0603 from SM-752 data"
  rect 1x0.95 smd: 1(-0.8,0) 2(0.8,0)
  silkscreen extent -1.52,-0.69 1.52,0.69, body extent -0.87,-0.47 0.87,0.47, height 1
0805_HV1 [mm] "Custom footprint based on analyzing multiple manufacturer recommendations"
  rrect10% 1x1.25 smd: 1(-1,0) 2(1,0)
  silkscreen extent -0.2,-0.75 0.2,0.75, body extent -1.1,-0.72 1.1,0.73, height 1.45
1206 [mm] "1206 from SM-752 data"
  rect 1.3x1.85 smd: 1(-1.45,0) 2(1.45,0)
  silkscreen extent -2.4,-1.21 2.4,1.21, body extent -1.7,-0.9 1.7,0.9, height 1.35
1206_180 [mm] "1206_180"
  rect 1.1x1.6 smd: 1(-1.7,0) 2(1.7,0)
  silkscreen extent -0.9,-1 0.9,1, body extent -1.75,-0.95 1.75,0.95, height 1.8
1812_180 [mm] "SMT, 2-Leads, Body 4.5x3.2mm"
  rect 1.85x4.36 smd: 1(-2.53,0) 2(2.53,0)
  silkscreen extent -3.75,-2.48 3.75,2.48, body extent -2.43,-1.75 2.42,1.75, height 1.8
2010 [mm] "Chip Capacitor, Body 5.08x2.54mm, IPC Medium Density"
  rect 1.6x2.7 smd: 1(-2.3,0) 2(2.3,0)
  silkscreen extent -3.42,-1.65 3.42,1.65, body extent -2.73,-1.45 2.73,1.45, height 1.66
2010L [mm]
  rect 1.2x2.7 smd: 1(-2.2,0) 2(2.2,0)
  silkscreen extent -1.2,-1.25 1.2,1.25, body extent -2.73,-1.45 2.73,1.45, height 1.66
AssemblyNote [mil] "Assembly Note"
AssemblyNoteLabel [mil] "Assembly Note for PCB Labels"
DBV0005A_N [mm] "SOT23, 5-Leads, Body 2.9x1.6mm, Pitch 0.95mm, Lead Span 2.8mm, IPC Medium Density"
  rrect17% 1x0.6 smd: 1(-1.375,0.95) 2(-1.375,0) 3(-1.375,-0.95) 4(1.375,-0.95) 5(1.375,0.95)
  silkscreen extent -1.63,-1.55 0.38,1.55, body extent -1.42,-1.46 1.42,1.46, height 1.09
DNK0008A [mm] "SON, 8-Leads, Body 5x6mm"
  rrect39% 0.86x0.51 smd paste-0.05 mask-0.05: 1(-2.82,1.905) 2(-2.82,0.635) 3(-2.82,-0.635) 4(-2.82,-1.905) 5(2.82,-1.905) 6(2.82,-0.635) 7(2.82,0.635) 8(2.82,1.905)
  rrect8% 1.48x1.27 on Top Paste: 9(-0.18,-1.47) 9(-0.18,0) 9(-0.18,1.47) 9(1.5,-1.47) 9(1.5,0) 9(1.5,1.47)
  rrect5% 4.34x4.6 smd paste-3 mask-0.05: 9(1.08,0)
  silkscreen extent -3.2,-2.7 3.2,2.7, body extent -3.05,-2.55 3.05,2.55, height 1.06
ESD_Overlay_Small [mil]
  silkscreen extent -62,-48 64,61
FC_630x1120 [mm] "TH, 2-Leads, Dia 6.3mm, Pin Spacing 2.5mm"
  rect 1.3x1.3 hole 0.8: 1(-1.25,0)
  round 1.3 hole 0.8: 2(1.25,0)
  silkscreen extent -3.4,-3.4 3.4,3.4, body extent -3.37,-3.39 3.4,3.39, height 12.21
FCC_disclaimer [mil]
Fiducial10-30 [mm]
  round 1 smd mask+1: 1(0,0)
  Top Layer keep-out circle w1.678: c0,0 r0.75
IEC_Caution_Small [mil]
  silkscreen extent -107,-93 107,92
IEC_HighVoltage_Small [mil]
  silkscreen extent -107,-88 107,97
IEC_HotSurface_Small [mil]
  silkscreen extent -107,-93 107,92
Keystone5002 [mil] "For Keystone 500x miniature loop terminals"
  round 80 hole 40: 1(0,0)
  silkscreen extent -52,-52 52,52, body extent -49,-49 49,49, height 182
MUB10A_N [mm] "TSSOP, 10-Leads, Body 3x3mm, Pitch 0.5mm, IPC Medium Density"
  oval 1.7x0.3 smd: 1(-2.05,1) 2(-2.05,0.5) 3(-2.05,0) 4(-2.05,-0.5) 5(-2.05,-1) 6(2.05,-1) 7(2.05,-0.5) 8(2.05,0) 9(2.05,0.5) 10(2.05,1)
  silkscreen extent -2.17,-1.6 0.8,1.82, body extent -1.6,-1.6 1.6,1.6, height 1.09
NHG_1000x2000 [mm] "PANASONIC"
  rect 1.55x1.55 hole 0.85: 1(-2.5,0)
  round 1.55 hole 0.85: 2(2.5,0)
  silkscreen extent -5.26,-5.26 5.26,5.26, body extent -5.21,-5.24 5.24,5.24, height 22.01
PhoenixConact_1727010 [mm]
  rect 1.7x1.7 hole 1.1: 1(-1.905,0)
  round 1.7 hole 1.1: 2(1.905,0)
  silkscreen extent -4.8,-3.6 3.81,3.6, body extent -3.81,-3.6 3.81,3.7, height 8.52
PowerDI123 [mm] "Diodes Inc recommended land pattern, document number DS30628 Rev. 6-2"
  rect 2.2x1.4 smd: 1(-1.275,0)
  rect 0.9x1.4 smd: 2(1.275,0)
  silkscreen extent -3.1,-1.09 1.76,1.09, body extent -2.37,-0.96 1.53,0.97, height 1
SOD-123 [mm] "On Semi recommended land pattern"
  rect 0.915x1.22 smd: 1(-1.637,0) 2(1.637,0)
  silkscreen extent -2.74,-1.17 2.03,1.17, body extent -1.93,-0.9 1.93,0.9, height 1.35
SOD-323 [mm] "NXP recommended land pattern"
  rect 0.6x0.6 smd paste-0.05: 1(-1.1,0) 2(1.1,0)
  silkscreen extent -2.06,-0.86 1.53,0.86, body extent -1.3,-0.67 1.3,0.68, height 1.1
SOT-23 [mm] "SOT23, 3-Leads, Body 2.9x1.3mm, Pitch 0.95mm, Lead Span 2.5mm, IPC Medium Density"
  rrect50% 1x0.6 smd: 1(-1.2,0.95) 2(-1.2,-0.95) 3(1.2,0)
  silkscreen extent -1.62,-1.5 0.7,1.5, body extent -1.16,-1.45 1.21,1.45, height 1
TI_Symbol_Overlay_Small [mil]
  silkscreen extent -90,-88 91,88
TNPW0603 [mm] "Vishay"
  rect 0.5x0.9 smd: 1(-0.75,0) 2(0.75,0)
  silkscreen extent -0.2,-0.6 0.2,0.6, body extent -0.85,-0.47 0.85,0.47, height 0.55
TO-277A [mm] "Vishay"
  rect 1.4x1.27 smd: 1(-1.04,1.83) 2(1.04,1.83)
  rect 4.72x4.8 smd: 3(0,-1.883)
  silkscreen extent -2.32,2.26 -2.12,2.46, body extent -2.35,-4.2 2.4,2.45, height 1.2
Wurth_EE16_7_5_5278 [mm] "TH, 10-Leads, Body 16.5x18.5mm"
  rrect50% 1.65x1.65 hole 1.1: 1(-6.1,6.75) 2(-6.1,4.05)
  round 1.65 hole 1.1: 3(-6.1,1.35) 4(-6.1,-1.35) 5(-6.1,-4.05) 6(-6.1,-6.75) 7(6.1,-5.25) 8(6.1,-1.75) 9(6.1,1.75) 10(6.1,5.25)
  body extent -7.74,-8.81 7.74,8.81, height 17.73

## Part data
C1 C10 C22 C31 C43 C52: "CAP, CERM, 33 pF, 500 V,+/- 5%, C0G/NP0, 1206", Cap_Case=1206, Manufacturer=AVX, Supplier Part Number 1=12067A330JAT2A-ND, TempCo=C0G/NP0, Tolerance_%=5, Value2=500V, ValueDisplayed=33pF
C2 C23 C44: library part EEU-FC1V470, "CAP, AL, 180 µF, 35 V, +/- 20%, TH", Cap_Case=6.3x11.2mm, Manufacturer=Rubycon, Supplier Part Number 1=35TXW180MEFC6.3X25-ND, Tolerance_%=20, Value2=35V, ValueDisplayed=180µF
C3 C4 C24 C25 C45 C46: "CAP, CERM, 10 µF, 50 V,+/- 10%, X5R, 1206", Cap_Case=1206, Manufacturer=MuRata, Supplier Part Number 1=490-5961-1-ND, TempCo=X5R, Tolerance_%=10, Value2=50V, ValueDisplayed=10µF
C5 C6 C11 C12 C26 C27 C32 C33 C47 C48 C53 C54: library part C4532X7R1H105K160KA, "CAP, CERM, 1 µF, 250 V,+/- 20%, X7T, 1812", Cap_Case=1812, Manufacturer="TDK Corporation", Supplier Part Number 1=445-6835-2-ND, TempCo=X7T, Tolerance_%=20, Value1="0.007217 ohm", Value2=250V, ValueDisplayed=1µF
C7 C13 C28 C34 C49 C55: library part ECA-2AHG101, "CAP, AL, 82 µF, 160 V, +/- 20%, TH", Cap_Case=10x20mm, Manufacturer=Nichicon, Supplier Part Number 1=493-6989-ND, Tolerance_%=20, Value2=160V, ValueDisplayed=82µF
C8 C29 C50: "CAP, CERM, 1 µF, 100 V,+/- 10%, X7R, 1206", Cap_Case=1206, Manufacturer=MuRata, Supplier Part Number 1=490-3909-1-ND, TempCo=X7R, Tolerance_%=10, Value2=100V, ValueDisplayed=1µF
C9 C15 C17 C20 C30 C36 C38 C41 C51 C57 C59 C62 C67 C68 C69: "CAP, CERM, 0.1 µF, 50 V,+/- 10%, X7R, 0603", Cap_Case=0603, Manufacturer=MuRata, Supplier Part Number 1=490-1519-1-ND, TempCo=X7R, Tolerance_%=10, Value2=50V, ValueDisplayed=0.1µF
C14 C35 C56: library part GRM21BC81C226ME44L, "CAP, CERM, 22 µF, 35 V,+/- 20%, X5R, 0805", Cap_Case=0805, Manufacturer="TDK Corporation", Supplier Part Number 1=445-14428-2-ND, TempCo=X6S, Tolerance_%=20, Value2=35V, ValueDisplayed=22µF
C16 C37 C58: "CAP, CERM, 1 µF, 50 V,+/- 10%, X7R, 0603", Cap_Case=0603, Manufacturer="Taiyo Yuden", Supplier Part Number 1=587-3247-1-ND, TempCo=X7R, Tolerance_%=10, Value2=50V, ValueDisplayed=1µF
C18 C39 C60: "CAP, CERM, 2200 pF, 50 V,+/- 10%, X5R, 0402", Cap_Case=0402, Manufacturer=MuRata, Supplier Part Number 1=GRM155R61H222KA01D-ND, TempCo=X5R, Tolerance_%=10, Value2=50V, ValueDisplayed=2200pF
C19 C40 C61: "CAP, CERM, 4.7 µF, 10 V,+/- 10%, X5R, 0603", Cap_Case=0603, Manufacturer=AVX, Supplier Part Number 1=478-7943-1-ND, TempCo=X5R, Tolerance_%=10, Value2=10V, ValueDisplayed=4.7µF
C21 C42 C63 C64 C65 C66: "CAP, CERM, 1 µF, 25 V,+/- 10%, X7R, 0603", Cap_Case=0603, Manufacturer=Kemet, Supplier Part Number 1=399-7376-1-ND, TempCo=X7R, Tolerance_%=10, Value2=25V, ValueDisplayed=1µF
D1 D4 D6 D9 D11 D14: "Diode, Hyperfast, 600 V, 6 A, AEC-Q101, TO-277A", Manufacturer=Vishay-Semiconductor, Supplier Part Number 1=VS-6ESH06HM3/86AGICT-ND, Value1=6A, Value2=1.05V
D2 D7 D12: "Diode, Schottky, 100 V, 1 A, PowerDI123", Manufacturer="Diodes Inc.", Supplier Part Number 1=DFLS1100DICT-ND, Value1=1A, Value2=0.77V
D3 D8 D13: "Diode, Schottky, 30 V, 0.2 A, SOD-123", Manufacturer="Diodes Inc.", Supplier Part Number 1=BAT42WDICT-ND, Value1=0.2A, Value2=1V
D5 D10 D15: "Diode, Zener, 12 V, 200 mW, SOD-323", Manufacturer="Diodes Inc.", Power_W=0.2, Supplier Part Number 1=MMSZ5242BS-FDICT-ND, Value1=0.2W
FID1 FID2 FID3 FID4 FID5 FID6: "Fiducial mark.  There is nothing to buy or mount.", Manufacturer=N/A
J1 J2 J3 J5 J6 J8 J9: "Conn Term Block, 2POS, 3.81mm, TH", Manufacturer="Phoenix Contact", Supplier Part Number 1=277-1947-ND
Logo1: library part TI_Logo, "Texas Instrument Corporate Signature"
LOGO2 LOGO9: library part IEC_HotSurface, "IEC 61010-1 Hot Surface Warning"
Logo3: library part FCC_disclaimer, "FCC_disclaimer"
Logo4: library part ESD_Susceptible, "ESD Susceptible Symbol"
Logo5 Logo6: library part IEC_Caution, "IEC 61010-1 Caution Warning"
LOGO7 LOGO8: library part IEC_HighVoltage, "IEC 61010-1 High Voltage Warning"
Q1 Q5 Q9: "MOSFET, N-CH, 100 V, 17 A, DNK0008A (VSON-CLIP-8)", Alternate Manufacturer=None, Manufacturer="Texas Instruments", Supplier Part Number 1=296-37478-6-ND, Value1="? ohm", Value2="48 nC"
Q2 Q6 Q10: library part "MMBT2907ALT1G, ON Semiconductor", "Transistor, PNP, 60 V, 0.6 A, SOT-23", Manufacturer="ON Semiconductor", Supplier Part Number 1=MMBT2907ALT1GOSCT-ND, Value1="0.6 A"
Q3 Q4 Q7 Q8 Q11 Q12: library part "DNBT8105-7, Diodes Inc.", "Transistor, NPN, 60 V, 1 A, AEC-Q101, SOT-23", Manufacturer="Diodes Inc.", Supplier Part Number 1=DNBT8105DICT-ND, Value1="1 A", Value2=300
R1 R7 R30 R36 R59 R65: "RES, 470, 5%, 0.25 W, 1206", Manufacturer=Vishay-Dale, Power_W=0.25, Supplier Part Number 1=541-470ECT-ND, TempCo="200 ppm/C", Tolerance_%=5, Value1=5%, Value2=0.25W, Value_Code=470R, ValueDisplayed=470
R2 R31 R60: "RES, 5.11 k, 0.1%, 0.1 W, AEC-Q200 Grade 1, 0603", Manufacturer=Vishay-Dale, Power_W=0.1, Supplier Part Number 1=TNP5.11KAACT-ND, TempCo="25 ppm/C", Value1=0.1%, Value2=0.1W, Value_Code=5k11, ValueDisplayed=5.11k
R3 R32 R61: "RES, 2.61 k, 1%, 0.75 W, AEC-Q200 Grade 0, 2010", Manufacturer=Vishay-Dale, Power_W=0.75, Supplier Part Number 1=541-2.61KACCT-ND, TempCo="100 ppm/C", Tolerance_%=1, Value1=1%, Value2=0.75W, Value_Code=2k61, ValueDisplayed=2.61k
R4 R33 R62: "RES, 402 k, 1%, 0.1 W, 0603", Manufacturer=Vishay-Dale, Power_W=0.1, Supplier Part Number 1=541-402KHCT-ND, TempCo="100 ppm/C", Tolerance_%=1, Value1=1%, Value2=0.1W, Value_Code=402k
R5 R34 R63: "RES, 10.0, 1%, 0.25 W, 0603", Manufacturer=Vishay-Dale, Power_W=0.25, Supplier Part Number 1=541-10.0SCT-ND, TempCo="100 ppm/C", Tolerance_%=1, Value1=1%, Value2=0.25W, Value_Code=10R0
R6 R35 R64: "RES, 1.0 M, 5%, 0.1 W, 0603", Manufacturer=Vishay-Dale, Power_W=0.1, Supplier Part Number 1=541-1.0MGCT-ND, TempCo="200 ppm/C", Tolerance_%=5, Value1=5%, Value2=0.1W, Value_Code=1M00, ValueDisplayed=1.0M
R8 R37 R66: "RES, 66.5 k, 1%, 0.1 W, 0603", Manufacturer=Vishay-Dale, Power_W=0.1, Supplier Part Number 1=541-66.5KHCT-ND, TempCo="100 ppm/C", Tolerance_%=1, Value1=1%, Value2=0.1W, Value_Code=66k5, ValueDisplayed=66.5k
R9 R38 R67: "RES, 4.7, 5%, 0.1 W, 0603", Manufacturer=Vishay-Dale, Power_W=0.1, Supplier Part Number 1=541-4.7GCT-ND, TempCo="200 ppm/C", Tolerance_%=5, Value1=5%, Value2=0.1W, Value_Code=4R70, ValueDisplayed=4.7
R10 R39 R68: "RES, 191 k, 1%, 0.1 W, 0603", Manufacturer=Vishay-Dale, Power_W=0.1, Supplier Part Number 1=541-191KHCT-ND, TempCo="100 ppm/C", Tolerance_%=1, Value1=1%, Value2=0.1W, Value_Code=191k
R11 R40 R69: "RES, 300, 5%, 0.1 W, 0603", Manufacturer=Vishay-Dale, Power_W=0.1, Supplier Part Number 1=541-300GCT-ND, TempCo="200 ppm/C", Tolerance_%=5, Value1=5%, Value2=0.1W, Value_Code=300R, ValueDisplayed=300
R12 R41 R70: "RES, 2.2 k, 5%, 0.1 W, AEC-Q200 Grade 0, 0603", Manufacturer=Panasonic, Power_W=0.1, Supplier Part Number 1=P2.2KGCT-ND, TempCo="200 ppm/C", Tolerance_%=5, Value1=5%, Value2=0.1W, Value_Code=2k20, ValueDisplayed=2.2k
R13 R42 R71: "RES, 0.015, 1%, 1 W, 2010", Manufacturer=Vishay-Dale, Power_W=1, Supplier Part Number 1=WSLF-.015CT-ND, TempCo="75 ppm/C", Value1=1%, Value2=1W, Value_Code=R015, ValueDisplayed=0.015
R14 R43 R72: "RES, 172 k, 0.5%, 0.1 W, 0603", Manufacturer="Yageo America", Power_W=0.1, TempCo="50 ppm/C", Tolerance_%=0.5, Value1=0.5%, Value2=0.1W, Value_Code=172k
R15 R44 R73: "RES, 22 k, 5%, 0.1 W, 0603", Manufacturer=Vishay-Dale, Power_W=0.1, Supplier Part Number 1=541-22KGCT-ND, TempCo="200 ppm/C", Tolerance_%=5, Value1=5%, Value2=0.1W, Value_Code=22k0, ValueDisplayed=22k
R16 R45 R74: "RES, 10.0 k, 1%, 0.1 W, 0603", Manufacturer=Vishay-Dale, Power_W=0.1, Supplier Part Number 1=541-10.0KHCT-ND, TempCo="100 ppm/C", Tolerance_%=1, Value1=1%, Value2=0.1W, Value_Code=10k0, ValueDisplayed=10.0k
R17 R21 R25: "RES, 390 k, 5%, 0.1 W, 0603", Manufacturer=Vishay-Dale, Power_W=0.1, Supplier Part Number 1=541-390KGCT-ND, TempCo="200 ppm/C", Tolerance_%=5, Value1=5%, Value2=0.1W, Value_Code=390k
R18 R47 R76: "RES, 1.0 k, 5%, 0.1 W, 0603", Manufacturer=Vishay-Dale, Power_W=0.1, Supplier Part Number 1=541-1.0KGCT-ND, TempCo="200 ppm/C", Tolerance_%=5, Value1=5%, Value2=0.1W, Value_Code=1k00, ValueDisplayed=1.0k
R19 R23 R26: "RES, 0, 5%, 0.063 W, 0402", Manufacturer=Vishay-Dale, Power_W=0.063, Supplier Part Number 1=541-0.0JCT-ND, TempCo="200 ppm/C", Tolerance_%=5, Value1=5%, Value2=0.063W, Value_Code=0000, ValueDisplayed=0
R20 R24 R27 R49 R53 R56 R78 R82 R85: "RES, 0, 5%, 0.75 W, AEC-Q200 Grade 0, 2010", Manufacturer=Vishay-Dale, Power_W=0.75, Supplier Part Number 1=541-0.0WCT-ND, TempCo=ppm/C, Tolerance_%=5, Value1=5%, Value2=0.75W, Value_Code=0000, ValueDisplayed=0
R22 R51 R80: "RES, 47 k, 5%, 0.25 W, 1206", Manufacturer=Vishay-Dale, Power_W=0.25, Supplier Part Number 1=541-47KECT-ND, TempCo="200 ppm/C", Tolerance_%=5, Value1=5%, Value2=0.25W, Value_Code=47k0, ValueDisplayed=47k
R28 R29 R57 R58 R86 R87: "RES, 47 k, 5%, 0.1 W, 0603", Manufacturer="Yageo America", Power_W=0.1, Supplier Part Number 1=311-47KGRCT-ND, TempCo="100 ppm/C", Tolerance_%=5, Value1=5%, Value2=0.1W, Value_Code=47k0, ValueDisplayed=47k
T1 T2 T3: library part CMP-0081056-1, "Transformer, 13 uH, TH", Manufacturer="Wurth Elektronik", ValueDisplayed=13µH
TP1 TP2 TP3 TP4 TP5 TP6 TP7 TP8 TP9 TP10 TP11 TP12: "Test Point, Miniature, White, TH", Color=White, Manufacturer=Keystone, Supplier Part Number 1=36-5002-ND
U1 U4 U7: "High Efficiency Low-Side N-Channel Controller for Switching Regulators, 10-pin MSOP, Pb-Free", Manufacturer="Texas Instruments", PackageTopMarking=ZXTT*SJPB, PowerWise=N, Supplier Part Number 1=LM3481MMX-ND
